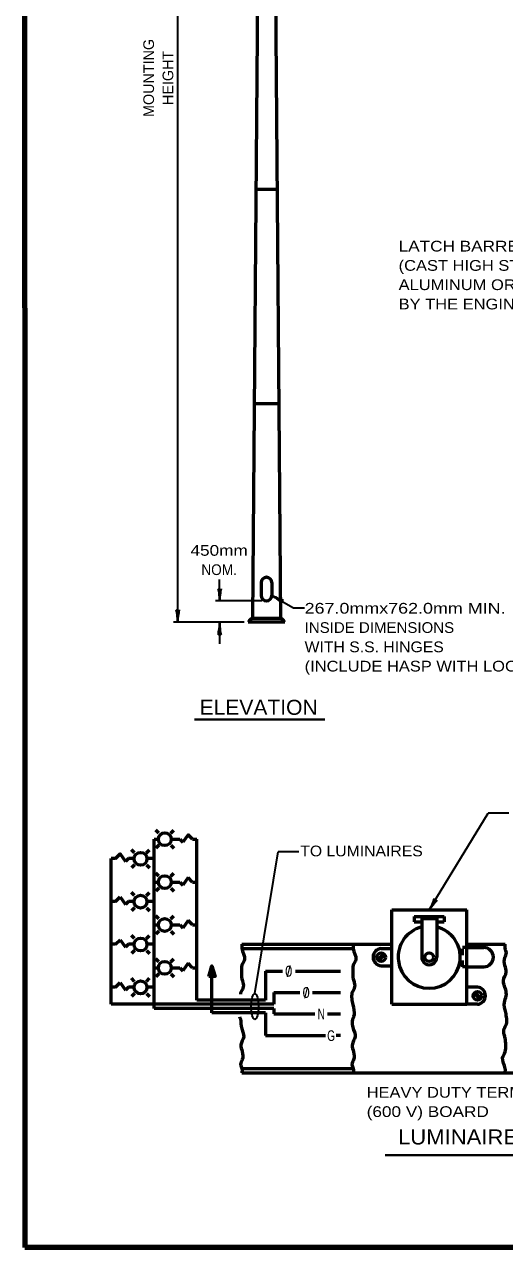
# Model space of a CAD drawing. Extents: x -24 to 689, y -7 to 446.
# Drawn here: x 23.7 to 135.8, y 2.2 to 287.5 of the extents above; entities that cross this region are included whole.
import ezdxf
from ezdxf.enums import TextEntityAlignment as Align

# ---------------------------------------------------------------- set-up
doc = ezdxf.new("R2010")
doc.units = 0
doc.linetypes.add('SHORT_DASHED', pattern=[2.7, 1.5, -1.2])
doc.layers.add('1', color=7, linetype='Continuous', lineweight=35)

msp = doc.modelspace()

# ---------------------------------------------------------------- linework, layer by layer
at = {"layer": '1'}
for p, q in [((59.446, 148.054), (59.446, 401.804)), ((69.252, 153.001), (69.252, 158.001)), ((81.446, 154.304), (86.495, 151.389)), ((79.196, 153.054), (68.252, 153.054)), ((86.495, 151.389), (89.043, 151.389)), ((74.946, 148.054), (58.446, 148.054)), ((69.252, 148.001), (69.252, 143.001)), ((118.19, 80.959), (131.948, 103.541)), ((136.806, 103.541), (131.948, 103.541)), ((77.458, 61.45), (82.907, 94.504)), ((87.765, 94.504), (82.907, 94.504))]:
    msp.add_line(p, q, dxfattribs=at)
at = {"layer": '1', "lineweight": 53}
for p, q in [((78.946, 399.063), (76.946, 149.054)), ((81.446, 399.056), (83.446, 149.054)), ((77.746, 249.054), (82.646, 249.054)), ((77.346, 199.054), (83.046, 199.054)), ((78.946, 157.304), (78.946, 154.304)), ((81.446, 157.304), (81.446, 154.304)), ((76.946, 149.054), (83.446, 149.054)), ((84.446, 148.054), (75.946, 148.054)), ((53.94, 57.959), (53.94, 97.459)), ((53.94, 97.459), (54.94, 97.459)), ((55.025, 98.873), (54.318, 99.58)), ((57.854, 98.873), (58.561, 99.58)), ((57.94, 97.459), (59.94, 97.459)), ((59.94, 97.459), (60.647, 96.752)), ((62.94, 97.459), (63.94, 97.459)), ((63.94, 59.959), (63.94, 97.459)), ((49.369, 94.31), (48.662, 95.018)), ((52.198, 94.31), (52.905, 95.018)), ((55.025, 96.044), (54.318, 95.337)), ((57.854, 96.044), (58.561, 95.337)), ((43.94, 58.959), (43.94, 92.959)), ((44.94, 92.959), (43.94, 92.959)), ((47.94, 92.959), (47.233, 92.252)), ((49.285, 92.959), (47.94, 92.959)), ((49.369, 91.482), (48.662, 90.775)), ((52.198, 91.482), (52.905, 90.775)), ((53.94, 92.959), (52.282, 92.959)), ((55.025, 88.873), (54.318, 89.58)), ((57.854, 88.873), (58.561, 89.58)), ((61.879, 88.519), (60.647, 86.752)), ((62.94, 87.459), (61.879, 88.519)), ((53.94, 87.459), (54.94, 87.459)), ((55.025, 86.044), (54.318, 85.337)), ((57.854, 86.044), (58.561, 85.337)), ((57.94, 87.459), (59.94, 87.459)), ((59.94, 87.459), (60.647, 86.752)), ((62.94, 87.459), (63.94, 87.459)), ((44.94, 82.959), (43.94, 82.959)), ((44.94, 82.959), (46, 84.019)), ((46, 84.019), (47.233, 82.252)), ((47.94, 82.959), (47.233, 82.252)), ((49.285, 82.959), (47.94, 82.959)), ((49.369, 84.31), (48.662, 85.018)), ((52.198, 84.31), (52.905, 85.018)), ((53.94, 82.959), (52.282, 82.959)), ((49.369, 81.482), (48.662, 80.775)), ((52.198, 81.482), (52.905, 80.775)), ((109.44, 58.959), (109.44, 80.959)), ((109.44, 80.959), (126.94, 80.959)), ((126.94, 58.959), (126.94, 80.959)), ((53.94, 77.459), (54.94, 77.459)), ((55.025, 78.873), (54.318, 79.58)), ((57.854, 78.873), (58.561, 79.58)), ((57.94, 77.459), (59.94, 77.459)), ((59.94, 77.459), (60.647, 76.752)), ((61.879, 78.519), (60.647, 76.752)), ((62.94, 77.459), (61.879, 78.519)), ((62.94, 77.459), (63.94, 77.459)), ((114.69, 79.459), (121.69, 79.459)), ((114.69, 79.459), (114.69, 78.209)), ((114.69, 78.209), (116.44, 78.209)), ((116.44, 78.959), (116.44, 69.959)), ((116.44, 78.959), (119.94, 78.959)), ((119.94, 78.959), (119.94, 69.959)), ((119.94, 78.209), (121.69, 78.209)), ((121.69, 79.459), (121.69, 78.209)), ((49.369, 74.31), (48.662, 75.018)), ((52.198, 74.31), (52.905, 75.018)), ((55.025, 76.044), (54.318, 75.337)), ((57.854, 76.044), (58.561, 75.337)), ((44.94, 72.959), (43.94, 72.959)), ((44.94, 72.959), (46, 74.019)), ((46, 74.019), (47.233, 72.252)), ((47.94, 72.959), (47.233, 72.252)), ((49.285, 72.959), (47.94, 72.959)), ((49.369, 71.482), (48.662, 70.775)), ((52.198, 71.482), (52.905, 70.775)), ((53.94, 72.959), (52.282, 72.959)), ((74.44, 71.959), (100.44, 71.959)), ((106.94, 71.959), (109.44, 71.959)), ((126.94, 72.959), (135.94, 72.959)), ((126.94, 72.209), (130.94, 72.209)), ((55.025, 68.873), (54.318, 69.58)), ((57.854, 68.873), (58.561, 69.58)), ((61.879, 68.519), (60.647, 66.752)), ((62.94, 67.459), (61.879, 68.519)), ((106.15, 69.346), (107.553, 70.749)), ((106.326, 69.169), (107.73, 70.572)), ((53.94, 67.459), (54.94, 67.459)), ((55.025, 66.044), (54.318, 65.337)), ((57.854, 66.044), (58.561, 65.337)), ((57.94, 67.459), (59.94, 67.459)), ((59.94, 67.459), (60.647, 66.752)), ((62.94, 67.459), (63.94, 67.459)), ((67.44, 56.959), (67.44, 67.324)), ((79.94, 66.709), (79.94, 59.959)), ((79.94, 66.709), (83.94, 66.709)), ((86.94, 66.709), (97.493, 66.709)), ((106.94, 67.959), (109.44, 67.959)), ((126.94, 67.709), (130.94, 67.709)), ((44.94, 62.959), (43.94, 62.959)), ((44.94, 62.959), (46, 64.019)), ((46, 64.019), (47.233, 62.252)), ((47.94, 62.959), (47.233, 62.252)), ((49.285, 62.959), (47.94, 62.959)), ((49.369, 64.311), (48.662, 65.018)), ((52.198, 64.311), (52.905, 65.018)), ((53.94, 62.959), (52.282, 62.959)), ((129.44, 62.959), (126.94, 62.959)), ((49.369, 61.482), (48.662, 60.775)), ((52.198, 61.482), (52.905, 60.775)), ((79.94, 59.959), (63.94, 59.959)), ((81.94, 61.709), (81.94, 58.959)), ((81.94, 61.709), (87.94, 61.709)), ((90.94, 61.709), (97.493, 61.709)), ((130.053, 60.169), (128.65, 61.572)), ((130.23, 60.346), (128.826, 61.749)), ((81.94, 58.959), (43.94, 58.959)), ((81.94, 57.959), (53.94, 57.959)), ((81.94, 57.959), (81.94, 56.725)), ((109.44, 58.959), (126.94, 58.959)), ((129.44, 58.959), (126.94, 58.959)), ((79.94, 56.959), (67.44, 56.959)), ((79.94, 56.959), (79.94, 51.694)), ((81.94, 56.725), (91.44, 56.725)), ((94.44, 56.725), (97.493, 56.725)), ((79.94, 51.694), (93.94, 51.694)), ((97.493, 51.694), (96.493, 51.694)), ((74.44, 43.959), (100.44, 43.959)), ((74.44, 42.959), (100.44, 42.959))]:
    msp.add_line(p, q, dxfattribs=at)
at = {"layer": '1', "lineweight": 40}
for p, q in [((63.338, 125.369), (93.827, 125.369)), ((107.891, 23.773), (207.154, 23.773))]:
    msp.add_line(p, q, dxfattribs=at)
at = {"layer": '1', "linetype": 'SHORT_DASHED', "lineweight": 53}
msp.add_line((126.94, 72.209), (125.94, 72.209), dxfattribs=at)
at = {"layer": '1', "lineweight": 158}
msp.add_line((683.413, 2.23), (23.747, 2.23), dxfattribs=at)
msp.add_lwpolyline([(683.413, 440.647), (23.663, 440.564), (23.747, 2.23)], dxfattribs=at)
at = {"layer": '1', "lineweight": 53}
for points in [[(62.94, 97.459), (61.879, 98.519), (60.647, 96.752)], [(44.94, 92.959), (46, 94.019), (47.233, 92.252)], [(74.44, 72.959), (100.44, 72.959), (109.44, 72.959)], [(100.44, 42.959), (135.94, 42.959), (223.44, 42.959)]]:
    msp.add_lwpolyline(points, dxfattribs=at)
at = {"layer": '1', "linetype": 'SHORT_DASHED', "lineweight": 53}
msp.add_lwpolyline([(126.94, 67.709), (125.94, 67.709), (125.94, 72.209)], dxfattribs=at)
at = {"layer": '1', "lineweight": 53}
msp.add_lwpolyline([(66.69, 65.459), (67.44, 67.959), (68.19, 65.459)], close=True, dxfattribs=at)
for centre, radius in [((56.44, 97.459), 1.5), ((50.784, 92.896), 1.5), ((56.44, 87.459), 1.5), ((50.784, 82.896), 1.5), ((56.44, 77.459), 1.5), ((50.784, 72.896), 1.5), ((56.44, 67.459), 1.5), ((106.94, 69.959), 1), ((118.19, 69.959), 1), ((50.784, 62.896), 1.5), ((129.44, 60.959), 1)]:
    msp.add_circle(centre, radius, dxfattribs=at)
for centre, radius, start, end in [((80.196, 157.304), 1.25, 0, 180), ((80.196, 154.304), 1.25, 180, 0), ((77.76, 147.24), 1.988, 114.16843, 155.83157), ((82.632, 147.24), 1.988, 24.16843, 65.83157), ((118.19, 69.959), 7.25, 103.96796, 76.03204), ((107.084, 69.959), 2.005, 94.11744, 265.88257), ((130.927, 69.959), 2.25, 270.32096, 89.67903), ((118.19, 69.917), 1.75, 178.63927, 1.36073), ((129.296, 60.959), 2.005, 274.11743, 85.88256)]:
    msp.add_arc(centre, radius, start, end, dxfattribs=at)
at = {"layer": '1', "lineweight": 40}
for centre, major_axis, ratio, start_param, end_param in [((68.975, 154.092), (0.156, -1.786), 0.122415, 0.8963533, 3.1415927), ((68.975, 154.092), (0.156, -1.786), 0.122415, 0.8963533, 3.1415927), ((69.463, 154.121), (-0.176, -1.756), 0.07063, 3.1407148, 5.41811), ((69.463, 154.121), (-0.176, -1.756), 0.07063, 3.1407148, 5.41811), ((82.31, 153.56), (-1.433, 1.03), 0.07063, 3.1407148, 5.41811), ((82.529, 153.997), (-1.625, 0.758), 0.122415, 0.8963533, 3.1415927), ((59.169, 149.145), (0.156, -1.786), 0.122415, 0.8963533, 3.1415927), ((59.169, 149.145), (0.156, -1.786), 0.122415, 0.8963533, 3.1415927), ((59.657, 149.174), (-0.176, -1.756), 0.07063, 3.1407148, 5.41811), ((59.657, 149.174), (-0.176, -1.756), 0.07063, 3.1407148, 5.41811), ((69.04, 146.88), (0.176, 1.756), 0.07063, 3.1407148, 5.41811), ((69.04, 146.88), (0.176, 1.756), 0.07063, 3.1407148, 5.41811), ((69.528, 146.91), (-0.156, 1.786), 0.122415, 0.8963533, 3.1415927), ((69.528, 146.91), (-0.156, 1.786), 0.122415, 0.8963533, 3.1415927), ((118.521, 82.034), (-0.796, -1.606), 0.122415, 0.8963533, 3.1415927), ((118.521, 82.034), (-0.796, -1.606), 0.122415, 0.8963533, 3.1415927), ((118.953, 81.806), (1.064, 1.409), 0.07063, 6.2823074, 8.5597026), ((118.953, 81.806), (1.064, 1.409), 0.07063, 6.2823074, 8.5597026)]:
    msp.add_ellipse(centre, major_axis=major_axis, ratio=ratio, start_param=start_param, end_param=end_param, dxfattribs=at)
at = {"layer": '1'}
msp.add_ellipse((77.458, 58.45), major_axis=(0, -3), ratio=0.286071, dxfattribs=at)
at = {"layer": '1', "lineweight": 53}
for points in [[(74.44, 72.978), (74.44, 71.978), (75.054, 69.457), (74.452, 68.073), (74.332, 66.449), (74.452, 64.884), (74.693, 64.042), (74.693, 62.718), (74.152, 61.575), (74.111, 61.325)], [(100.44, 72.959), (100.44, 71.959), (101.054, 69.437), (100.452, 68.054), (100.332, 66.429), (100.452, 64.865), (100.693, 64.022), (100.693, 62.699), (100.152, 61.555), (100.091, 60.292), (100.332, 58.848), (100.633, 56.501), (100.212, 54.997), (100.332, 53.553), (100.873, 51.387), (100.212, 49.462), (100.513, 47.897), (100.513, 46.032), (100.152, 44.949), (100.44, 43.959), (100.44, 42.959)], [(135.94, 42.959), (135.94, 43.959), (135.326, 46.48), (135.927, 47.864), (136.047, 49.489), (135.927, 51.053), (135.686, 51.895), (135.686, 53.219), (136.228, 54.362), (136.288, 55.626), (136.047, 57.07), (135.747, 59.416), (136.168, 60.921), (136.047, 62.365), (135.506, 64.531), (136.168, 66.456), (135.867, 68.02), (135.867, 69.886), (136.228, 70.969), (135.94, 71.959), (135.94, 72.959)], [(74.258, 54.138), (74.297, 54.808), (73.961, 56.006)], [(74.257, 54.151), (74.332, 53.573), (74.873, 51.407), (74.212, 49.481), (74.513, 47.917), (74.513, 46.051), (74.152, 44.968), (74.44, 43.978), (74.44, 42.978)]]:
    msp.add_spline(points, degree=3, dxfattribs=at)

# ---------------------------------------------------------------- texts
at = {"layer": '1'}
for s, p in [('MOUNTING', (53.925, 275.011)), ('HEIGHT', (58.425, 275.011))]:
    msp.add_text(s, height=2.5, rotation=90, dxfattribs=at).set_placement(p, align=Align.CENTER)
for s, width, p in [('LATCH BARREL OR LATCH CAM', 1.2, (111.044, 234.532)), ('(CAST HIGH STRENGTH', 1.15, (111.044, 230.032)), ('ALUMINUM OR AS APPROVED', 1.15, (111.044, 225.532)), ('BY THE ENGINEER', 1.15, (111.044, 221.032)), ('267.0mmx762.0mm MIN.', 1.25, (89.095, 150.075)), ('INSIDE DIMENSIONS', 1.05, (89.095, 145.575)), ('WITH S.S. HINGES', 1.1, (89.095, 141.075)), ('(INCLUDE HASP WITH LOCK)', 1.15, (89.095, 136.575)), ('HEAVY DUTY TERMINAL', 1.15, (103.579, 37.176)), ('(600 V) BOARD', 1.2, (103.579, 32.676))]:
    msp.add_text(s, height=2.5, dxfattribs=dict(at, width=width)).set_placement(p)
for s, height, width, p in [('450mm', 2.5, 1.2, (69.127, 163.573)), ('NOM.', 2.5, 0.95, (69.127, 159.073)), ('ELEVATION', 3.5, 1.05, (78.344, 126.473)), ('TO LUMINAIRES', 2.5, 1.1, (102.376, 93.468)), ('0', 2.5, 0.9, (85.375, 65.434)), ('0', 2.5, 0.9, (89.458, 60.454)), ('N', 2.5, 0.7, (92.978, 55.427)), ('G', 2.5, 0.7, (95.277, 50.396)), ('LUMINAIRE SUPPORT WIRING DETAIL', 3.5, 1.1, (158.106, 26.273))]:
    msp.add_text(s, height=height, dxfattribs=dict(at, width=width)).set_placement(p, align=Align.CENTER)
for p in [(85.374, 65.391), (89.43, 60.37)]:
    msp.add_text('/', height=2.5, dxfattribs=at).set_placement(p, align=Align.CENTER)

doc.saveas('drawing.dxf')
